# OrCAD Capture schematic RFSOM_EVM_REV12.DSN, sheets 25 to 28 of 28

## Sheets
25 18 QSFP: size A4
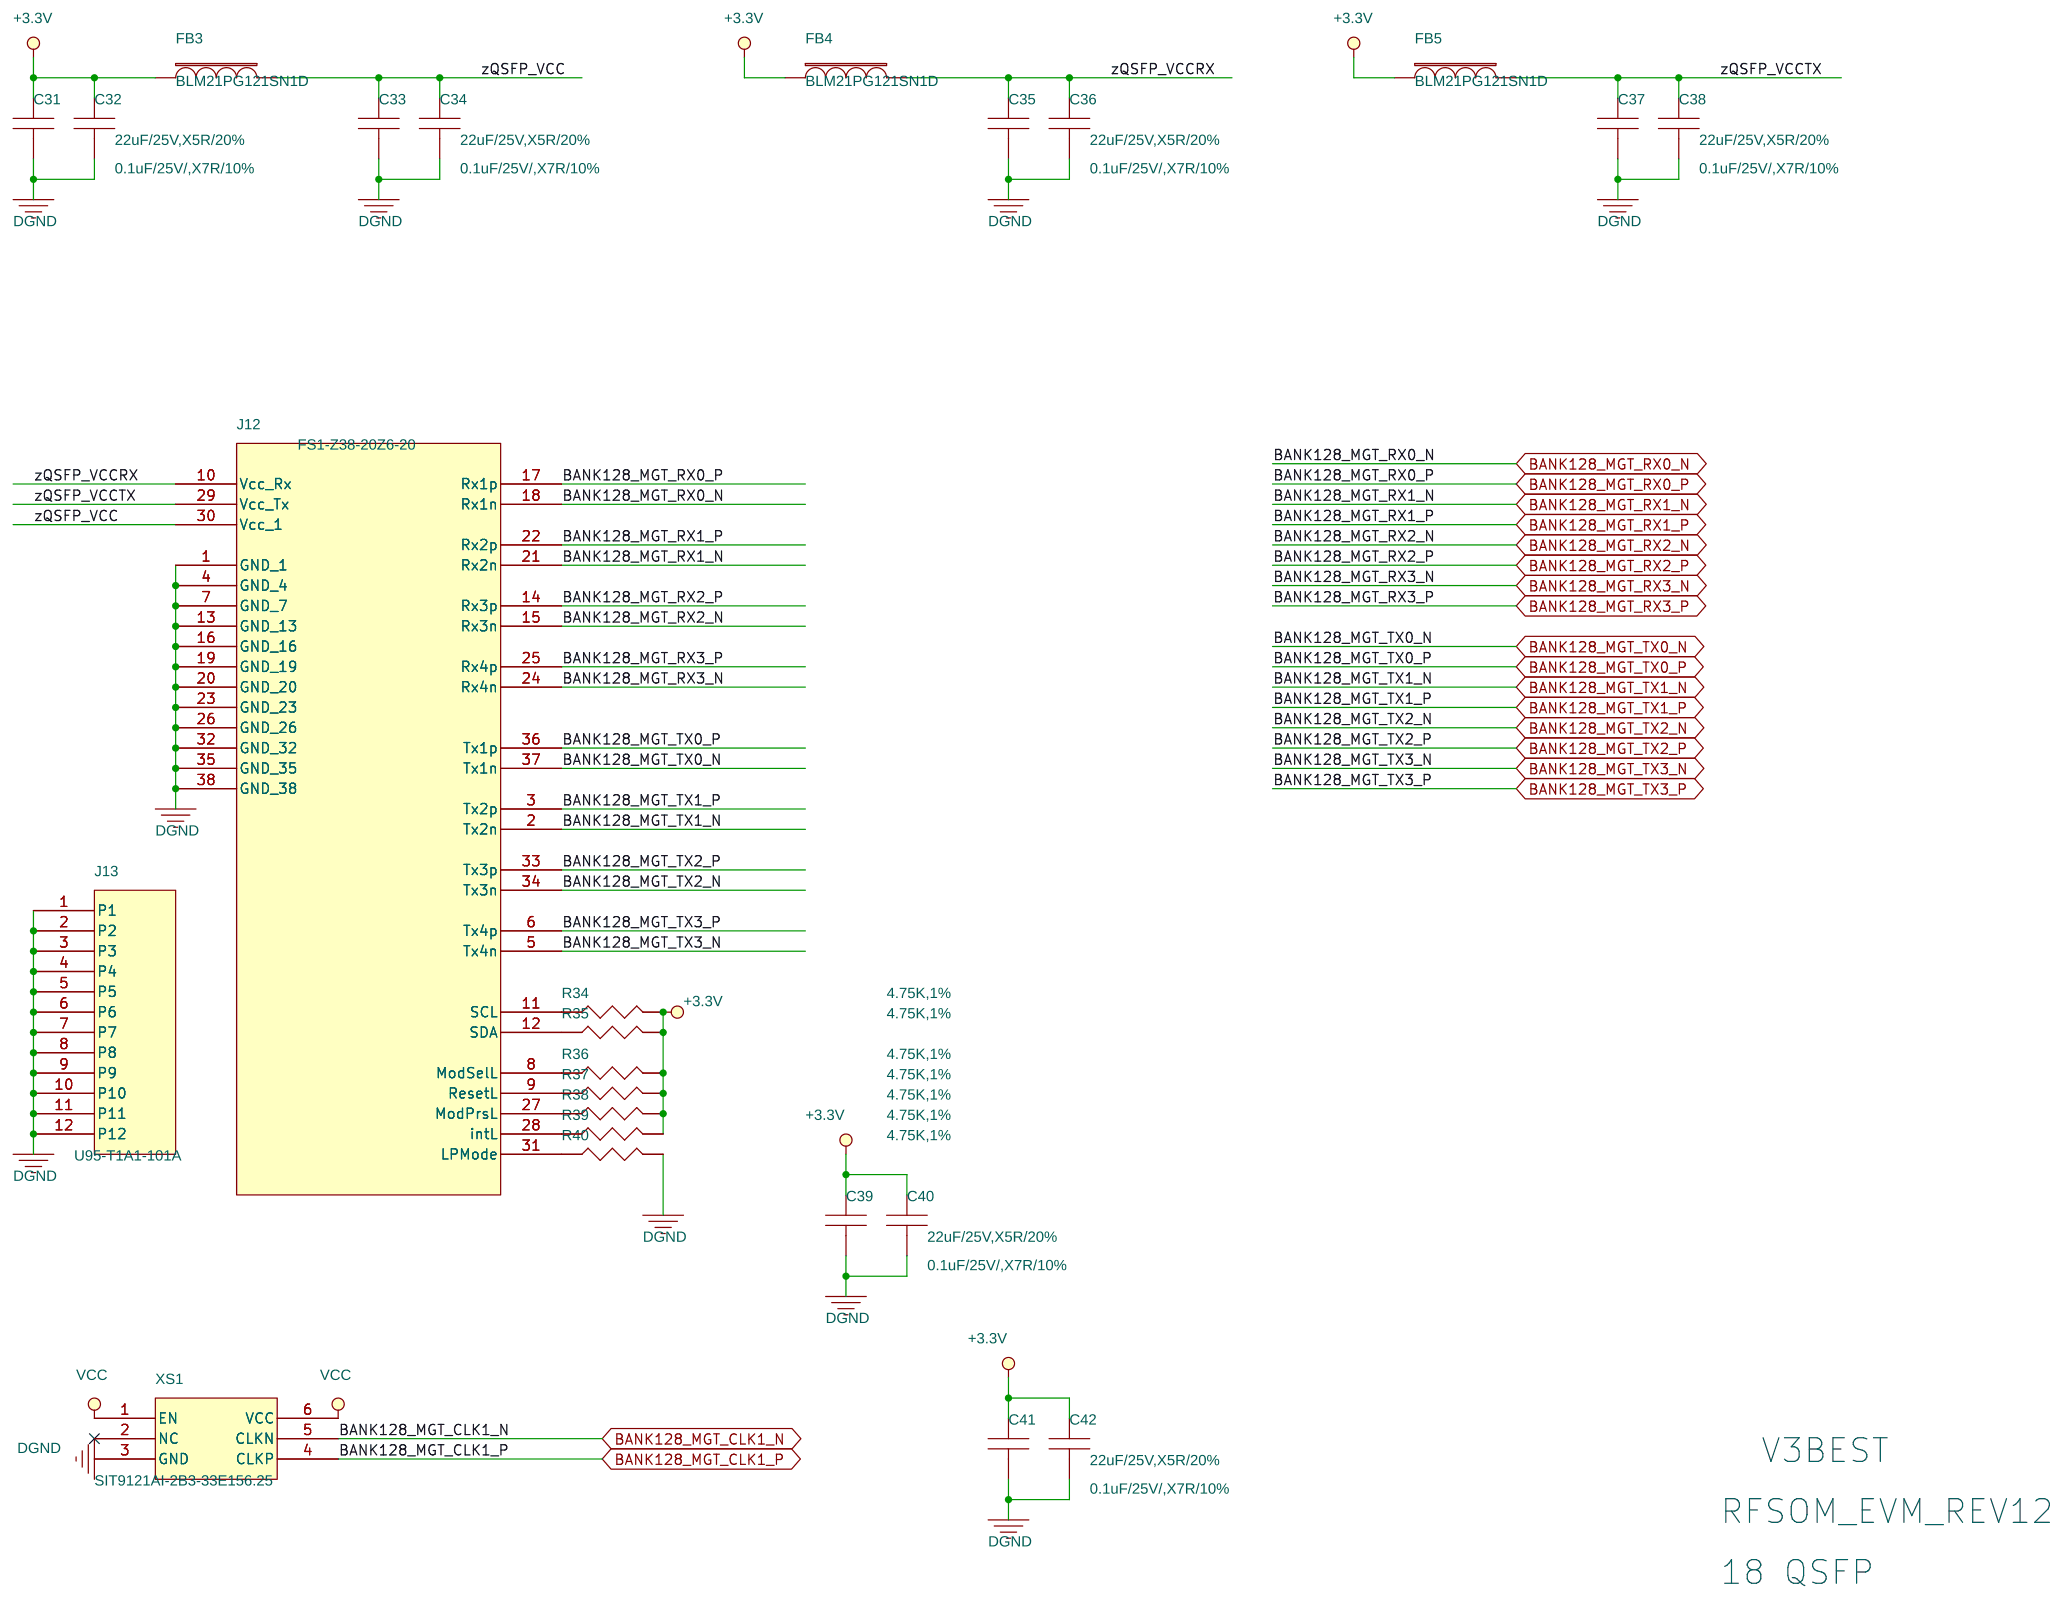
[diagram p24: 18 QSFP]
26 02 SYS_LOGIC
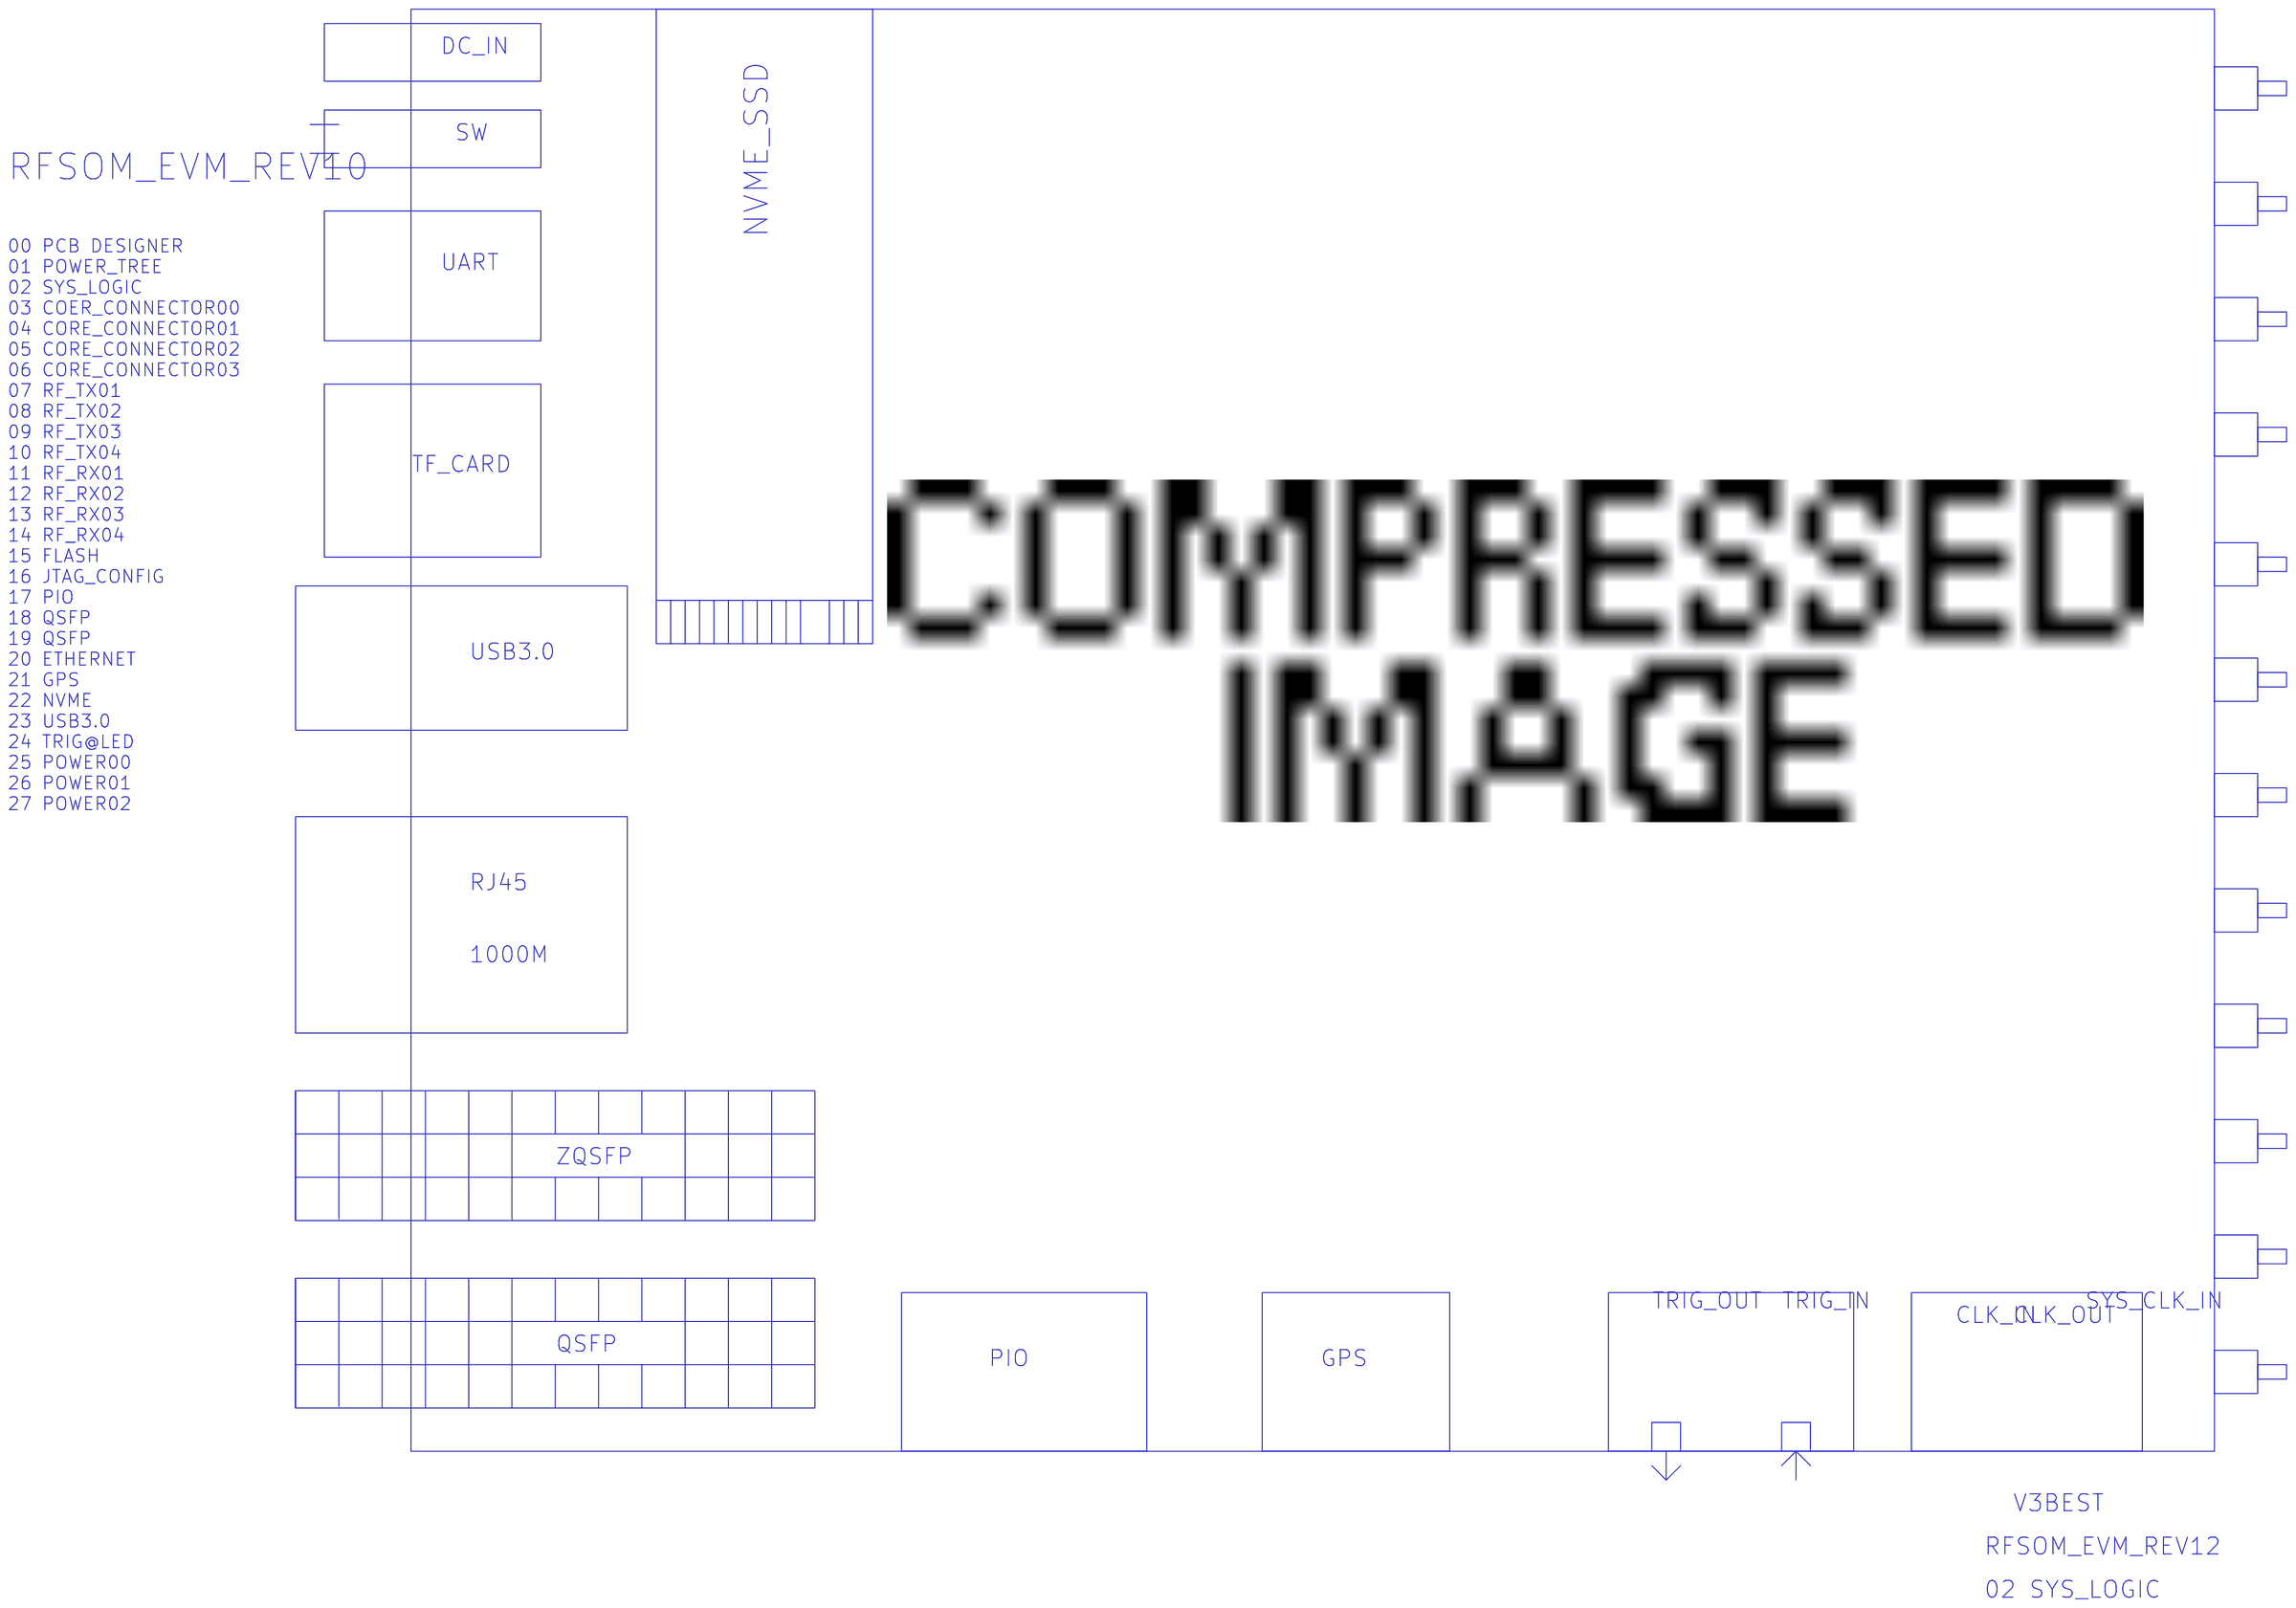
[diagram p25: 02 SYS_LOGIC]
27 16 JTAG_CONFIG: size A4
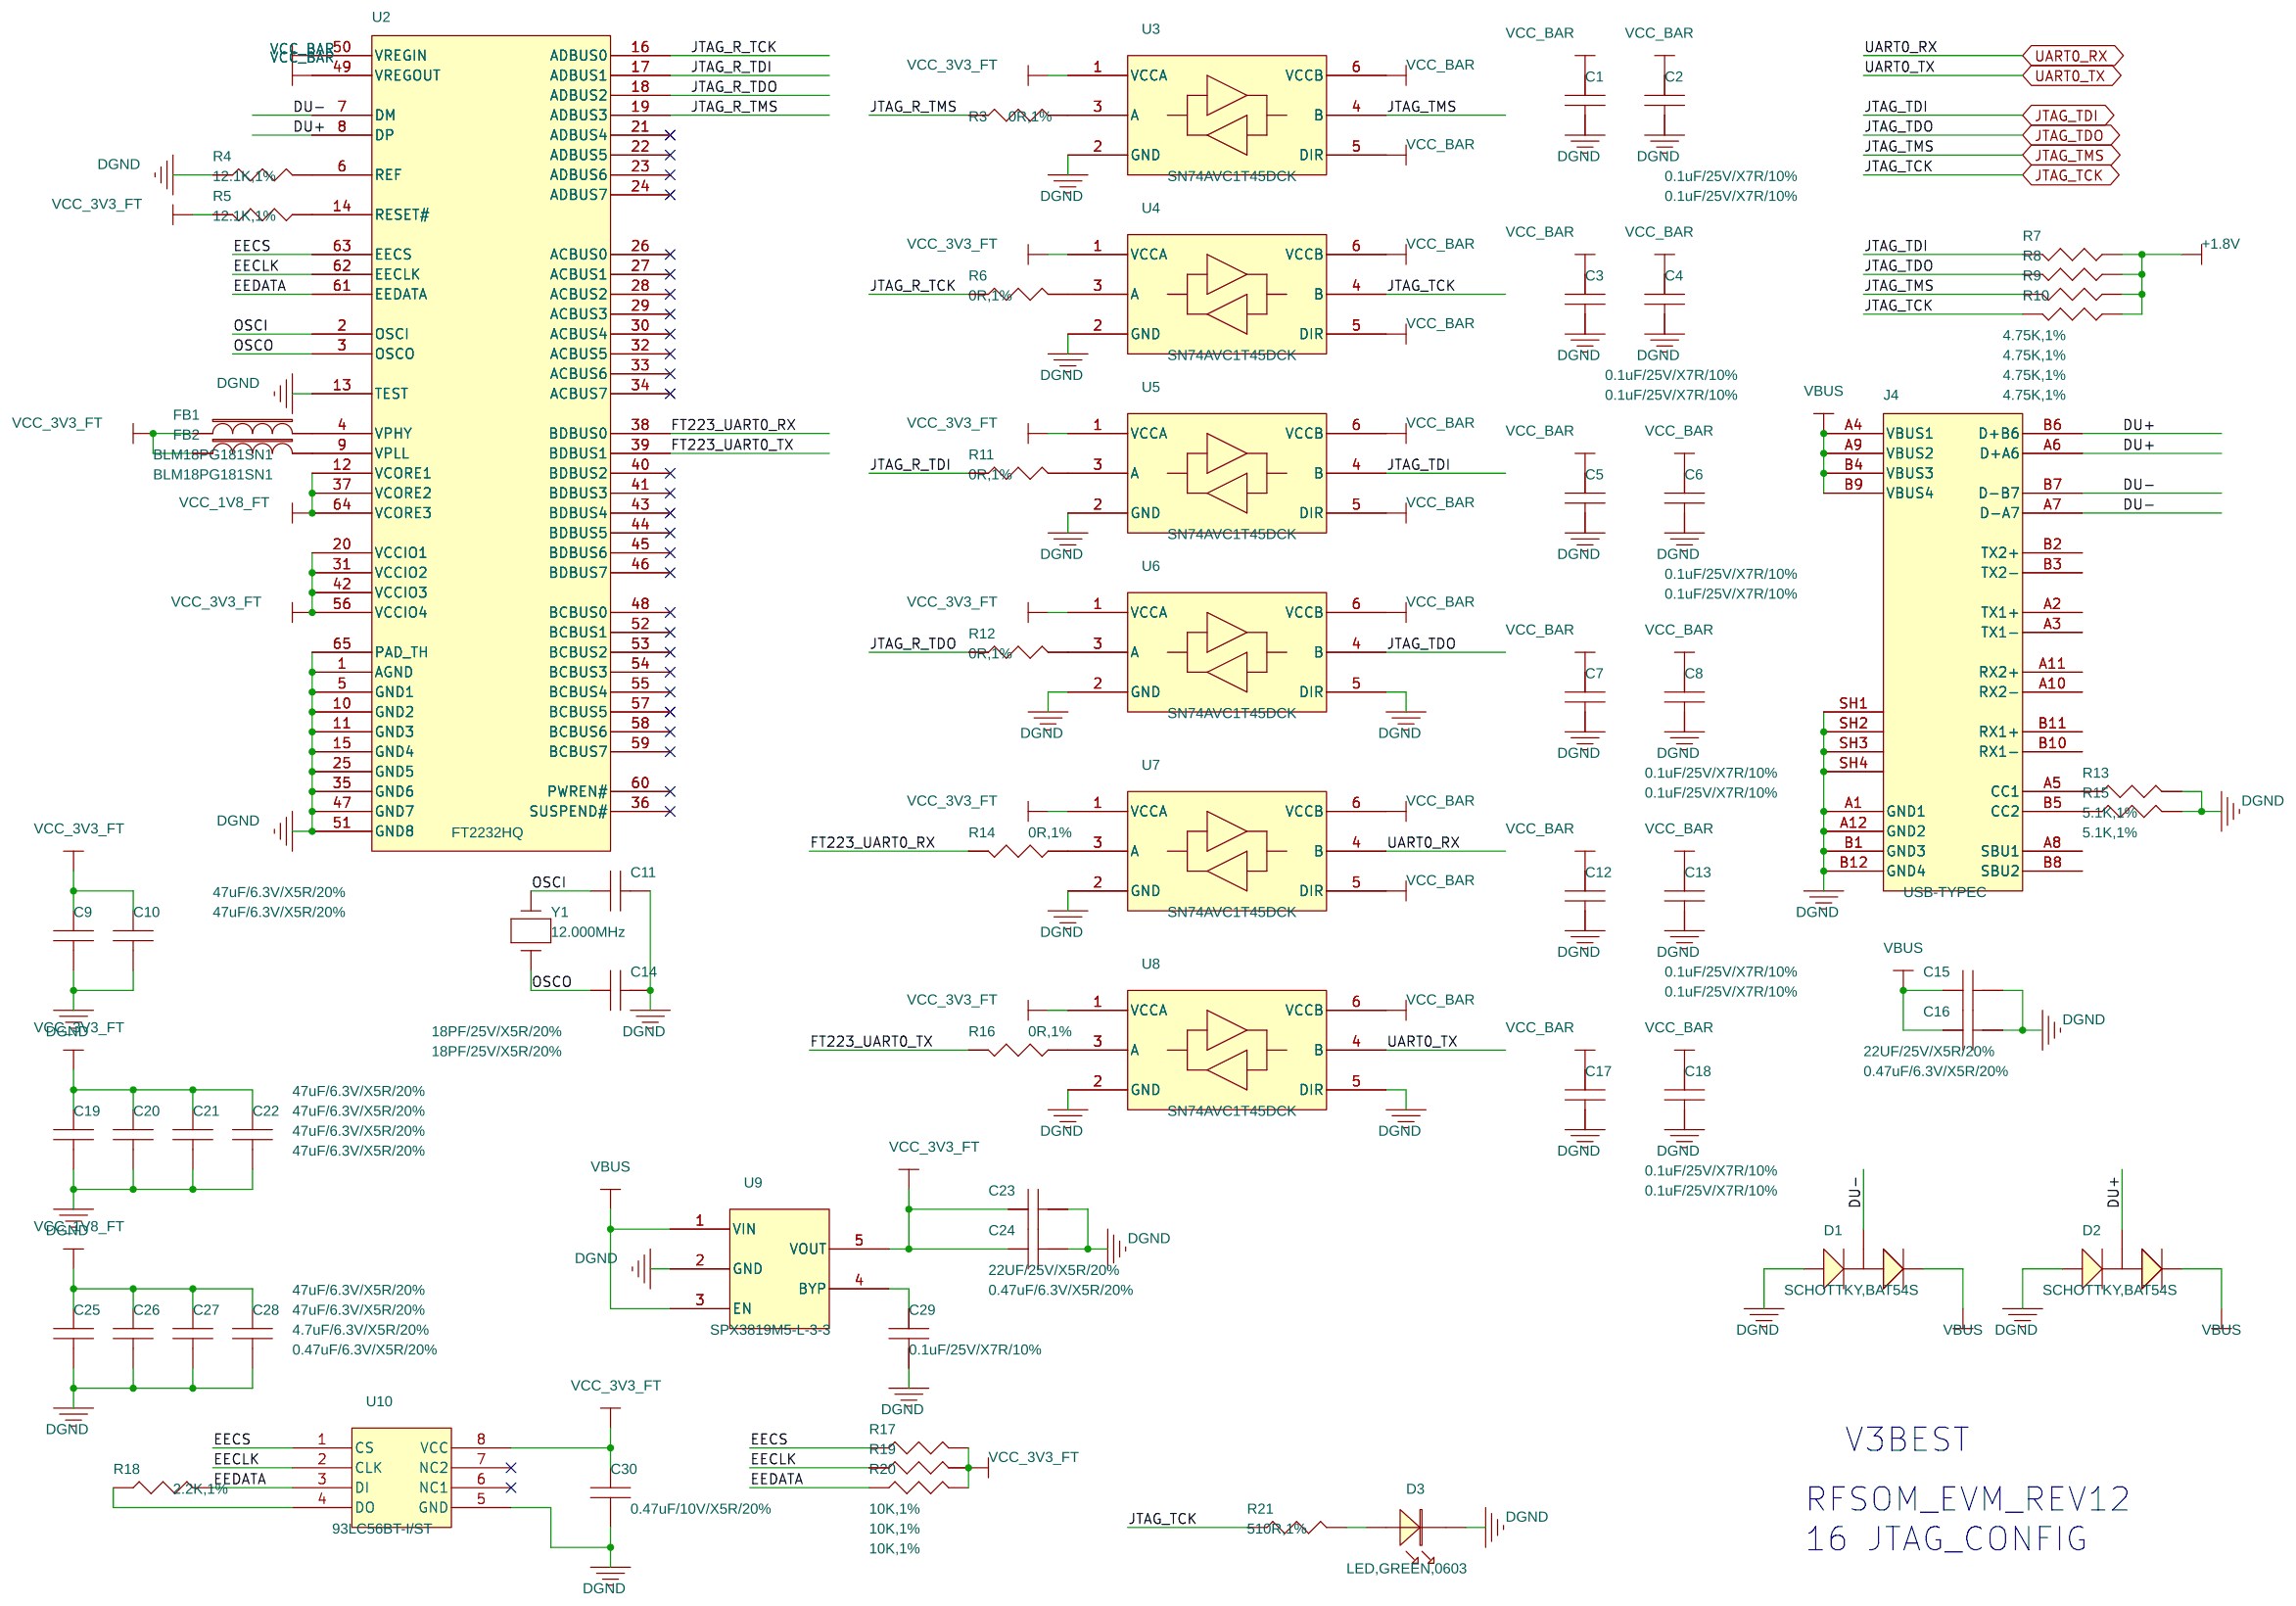
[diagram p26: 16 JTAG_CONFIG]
28 17 PIO: size A4
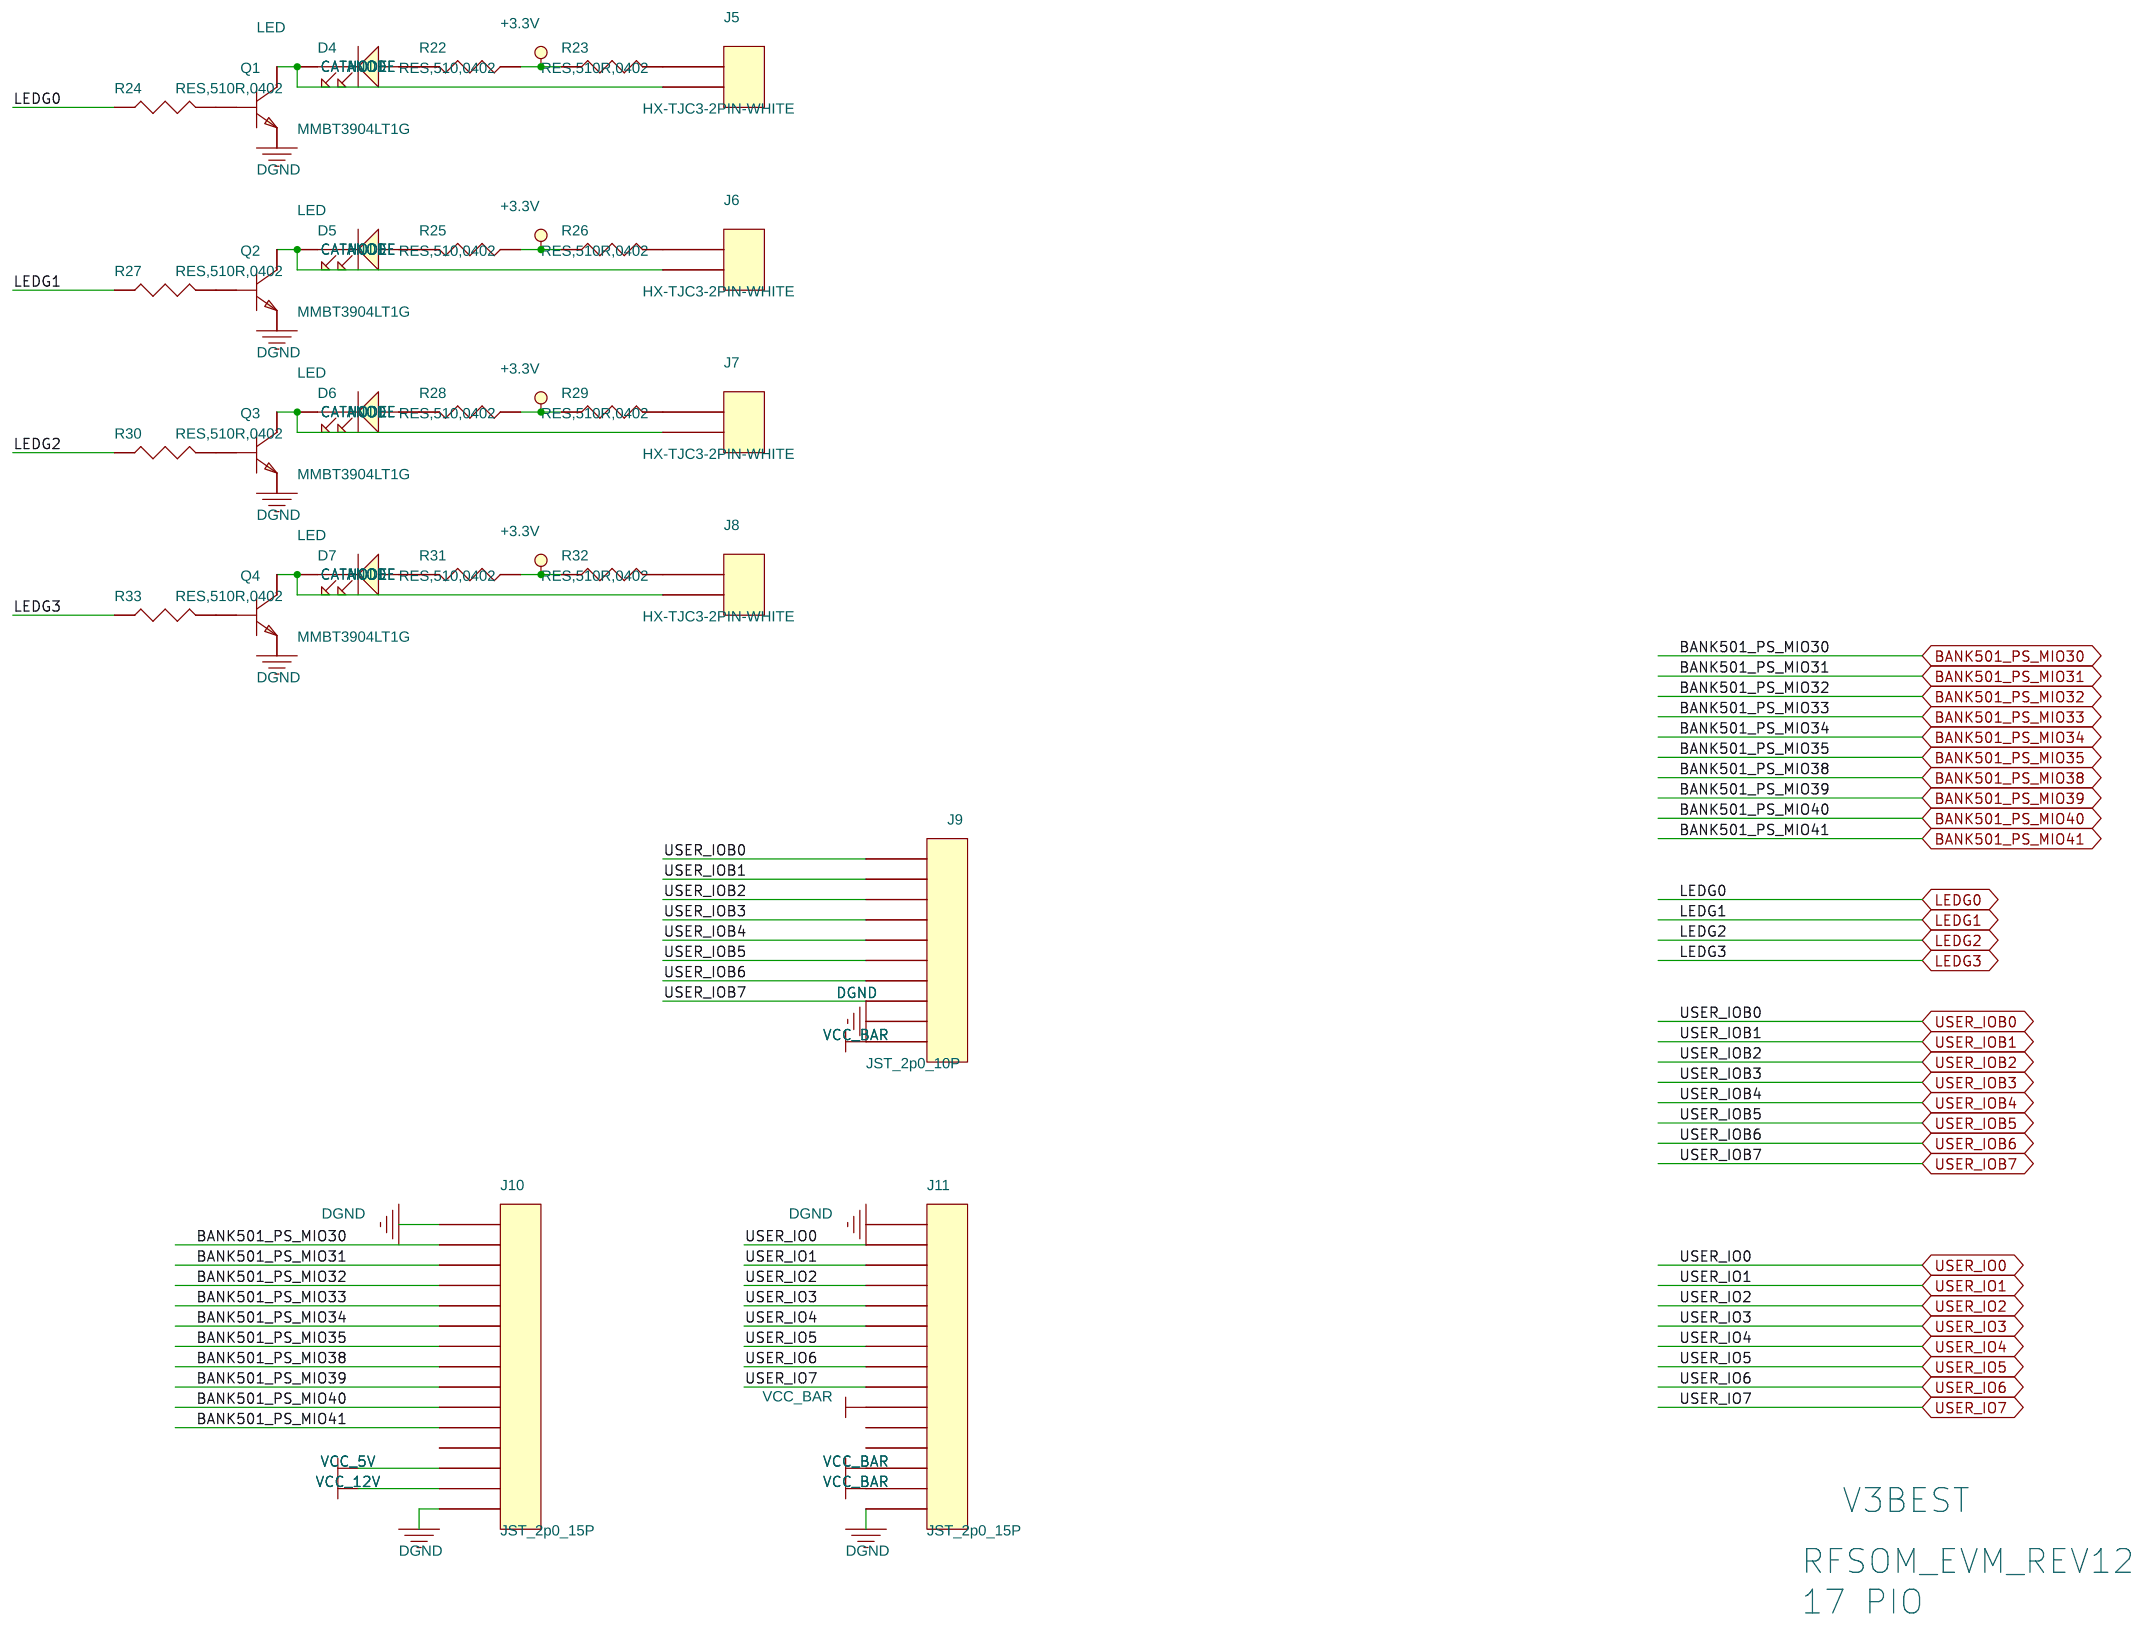
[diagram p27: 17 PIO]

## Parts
sheet 16 JTAG_CONFIG
C1  0.1uF/25V/X7R/10%  [C0402]
C2  0.1uF/25V/X7R/10%  [C0402]
C3  0.1uF/25V/X7R/10%  [C0402]
C4  0.1uF/25V/X7R/10%  [C0402]
C5  0.1uF/25V/X7R/10%  [C0402]
C6  0.1uF/25V/X7R/10%  [C0402]
C7  0.1uF/25V/X7R/10%  [C0402]
C8  0.1uF/25V/X7R/10%  [C0402]
C9  47uF/6.3V/X5R/20%  [C1206]
C10  47uF/6.3V/X5R/20%  [C1206]
C11  18PF/25V/X5R/20%  [C0402]
C12  0.1uF/25V/X7R/10%  [C0402]
C13  0.1uF/25V/X7R/10%  [C0402]
C14  18PF/25V/X5R/20%  [C0402]
C15  22UF/25V/X5R/20%  [C1206]
C16  0.47uF/6.3V/X5R/20%  [C0402]
C17  0.1uF/25V/X7R/10%  [C0402]
C18  0.1uF/25V/X7R/10%  [C0402]
C19  47uF/6.3V/X5R/20%  [C1206]
C20  47uF/6.3V/X5R/20%  [C1206]
C21  47uF/6.3V/X5R/20%  [C0402]
C22  47uF/6.3V/X5R/20%  [C0402]
C23  22UF/25V/X5R/20%  [C1206]
C24  0.47uF/6.3V/X5R/20%  [C0402]
C25  47uF/6.3V/X5R/20%  [C1206]
C26  47uF/6.3V/X5R/20%  [C1206]
C27  4.7uF/6.3V/X5R/20%  [C0402]
C28  0.47uF/6.3V/X5R/20%  [C0402]
C29  0.1uF/25V/X7R/10%  [C0402]
C30  0.47uF/10V/X5R/20%  [C0402]
D1  SCHOTTKY,BAT54S  [SOT23]
D2  SCHOTTKY,BAT54S  [SOT23]
D3  LED,GREEN,0603  [LED-0603]
FB1  BLM18PG181SN1  [FB0805]
FB2  BLM18PG181SN1  [FB0805]
J4  USB-TYPEC  [2012670005]
R3  0R,1%  [R0402]
R4  12.1K,1%  [R0402]
R5  12.1K,1%  [R0402]
R6  0R,1%  [R0402]
R7  4.75K,1%  [R0402]
R8  4.75K,1%  [R0402]
R9  4.75K,1%  [R0402]
R10  4.75K,1%  [R0402]
R11  0R,1%  [R0402]
R12  0R,1%  [R0402]
R13  5.1K,1%  [R0402]
R14  0R,1%  [R0402]
R15  5.1K,1%  [R0402]
R16  0R,1%  [R0402]
R17  10K,1%  [R0402]
R18  2.2K,1%  [0402R]
R19  10K,1%  [R0402]
R20  10K,1%  [R0402]
R21  510R,1%  [R0402]
U2  FT2232HQ  [QFN64]
U3  SN74AVC1T45DCK  [SC70_6]
U4  SN74AVC1T45DCK  [SC70_6]
U5  SN74AVC1T45DCK  [SC70_6]
U6  SN74AVC1T45DCK  [SC70_6]
U7  SN74AVC1T45DCK  [SC70_6]
U8  SN74AVC1T45DCK  [SC70_6]
U9  SPX3819M5-L-3-3  [SOT_25]
U10  93LC56BT-I/ST  [TSSOP8]
Y1  12.000MHz  [CRYSTAL_5X3P2]
sheet 17 PIO
D4  LED  [0603LED]
D5  LED  [0603LED]
D6  LED  [0603LED]
D7  LED  [0603LED]
J5  HX-TJC3-2PIN-WHITE  [HX-TJC3-2PIN-WHITE]
J6  HX-TJC3-2PIN-WHITE  [HX-TJC3-2PIN-WHITE]
J7  HX-TJC3-2PIN-WHITE  [HX-TJC3-2PIN-WHITE]
J8  HX-TJC3-2PIN-WHITE  [HX-TJC3-2PIN-WHITE]
J9  JST_2p0_10P  [SIP10_2-0MM_S]
J10  JST_2p0_15P  [SIP15_2-0MM_S]
J11  JST_2p0_15P  [SIP15_2-0MM_S]
Q1  MMBT3904LT1G  [SOT_23]
Q2  MMBT3904LT1G  [SOT_23]
Q3  MMBT3904LT1G  [SOT_23]
Q4  MMBT3904LT1G  [SOT_23]
R22  RES,510,0402  [R0402]
R23  RES,510R,0402  [R0402]
R24  RES,510R,0402  [R0402]
R25  RES,510,0402  [R0402]
R26  RES,510R,0402  [R0402]
R27  RES,510R,0402  [R0402]
R28  RES,510,0402  [R0402]
R29  RES,510R,0402  [R0402]
R30  RES,510R,0402  [R0402]
R31  RES,510,0402  [R0402]
R32  RES,510R,0402  [R0402]
R33  RES,510R,0402  [R0402]
sheet 18 QSFP
C31  22uF/25V,X5R/20%  [C1206]
C32  0.1uF/25V/,X7R/10%  [C0402]
C33  22uF/25V,X5R/20%  [C1206]
C34  0.1uF/25V/,X7R/10%  [C0402]
C35  22uF/25V,X5R/20%  [C1206]
C36  0.1uF/25V/,X7R/10%  [C0402]
C37  22uF/25V,X5R/20%  [C1206]
C38  0.1uF/25V/,X7R/10%  [C0402]
C39  22uF/25V,X5R/20%  [C1206]
C40  0.1uF/25V/,X7R/10%  [C0402]
C41  22uF/25V,X5R/20%  [C1206]
C42  0.1uF/25V/,X7R/10%  [C0402]
FB3  BLM21PG121SN1D  [FB0805]
FB4  BLM21PG121SN1D  [FB0805]
FB5  BLM21PG121SN1D  [FB0805]
J12  FS1-Z38-20Z6-20  [QSFP28_CON]
J13  U95-T1A1-101A  [U95-T1N1-101A]
R34  4.75K,1%  [R0402]
R35  4.75K,1%  [R0402]
R36  4.75K,1%  [R0402]
R37  4.75K,1%  [R0402]
R38  4.75K,1%  [R0402]
R39  4.75K,1%  [R0402]
R40  4.75K,1%  [R0402]
XS1  SIT9121AI-2B3-33E156.25  [XTALSMD_3225_DP]

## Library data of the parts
C1-C42 = CAP
D1 D2 = SCHOTTKY,BAT54S
D3 = LED,GREEN,0603
FB1 FB2 = BLM18PG181SN1D
J4 = USB-TYPEC
R3-R13 R15 R17 R19-R22 R25 R28 R31 = RES-H
R14 R16 R18 R23 R24 R26 R27 R29 R30 R32-R40 = RES
U2 = FT2232HQ
U3-U8 = SN74AVC1T45
U9 = SPX3819M5-L-3-3
U10 = 93LC56BT-I_ST
Y1 = CRYSTAL
D4-D7 = LED
J5-J8 = HX-TJC3-2PIN-WHITE
J9 = HEADER_10
J10 J11 = JST_2p0_15
Q1-Q4 = MMBT3904LT1G
FB3-FB5 = BLM21PG121SN1D
J12 = QSFP28-FS1-Z38-20Z6-20_0
J13 = U95-T1A1-101A
XS1 = SIT9121

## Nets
+1.8V: C2.1 C4.1 C6.1 C8.1 R7.1 R8.1 R9.1 R10.1 U3.6(VCCB) U4.6(VCCB) U5.6(VCCB) U6.6(VCCB) ; also on sheet 5 20 21
+3.3V: C13.1 C18.1 C31.1 C32.1 C39.1 C40.1 C41.1 C42.1 FB3.1 FB4.1 FB5.1 J11.10 R22.1 R23.1 R25.1 R26.1 R28.1 R29.1 R31.1 R32.1 R34.2 R35.2 R36.2 R37.2 R38.2 R39.2 U7.6(VCCB) U8.6(VCCB) XS1.1(EN) XS1.6(VCC) ; also on sheet 2 3 4 5 7 20 21 23 24
DGND: C1.2 C2.2 C3.2 C4.2 C5.2 C6.2 C7.2 C8.2 C9.2 C10.2 C11.2 C12.2 C13.2 C14.2 C15.2 C16.2 C17.2 C18.2 C19.2 C20.2 C21.2 C22.2 C23.2 C24.2 C25.2 C26.2 C27.2 C28.2 C29.2 C30.2 C31.2 C32.2 C33.2 C34.2 C35.2 C36.2 C37.2 C38.2 C39.2 C40.2 C41.2 C42.2 D1.1 D2.1 D3.2(K) J4.A1(GND1) J4.A12(GND2) J4.B1(GND3) J4.B12(GND4) J4.SH1 J4.SH2 J4.SH3 J4.SH4 J9.9 J10.1 J10.15 J11.1 J11.15 J12.1(GND) J12.4(GND) J12.7(GND) J12.13(GND) J12.16(GND) J12.19(GND) J12.20(GND) J12.23(GND) J12.26(GND) J12.32(GND) J12.35(GND) J12.38(GND) J13.1(P1) J13.2(P2) J13.3(P3) J13.4(P4) J13.5(P5) J13.6(P6) J13.7(P7) J13.8(P8) J13.9(P9) J13.10(P10) J13.11(P11) J13.12(P12) Q1.2(E) Q2.2(E) Q3.2(E) Q4.2(E) R4.1 R13.2 R15.2 R40.2 U2.1(AGND) U2.5(GND1) U2.10(GND2) U2.11(GND3) U2.13(TEST) U2.15(GND4) U2.25(GND5) U2.35(GND6) U2.47(GND7) U2.51(GND8) U2.65(PAD_TH) U3.2(GND) U4.2(GND) U5.2(GND) U6.2(GND) U6.5(DIR) U7.2(GND) U8.2(GND) U8.5(DIR) U9.2(GND) U10.5(GND) XS1.3(GND) ; also on sheet 2 3 4 5 6 7 8 9 10 11 12 13 14 15 16 18 20 21 23 24
VBUS: C15.1 C16.1 D1.2 D2.2 J4.A4(VBUS1) J4.A9(VBUS2) J4.B4(VBUS3) J4.B9(VBUS4) U9.1(VIN) U9.3(EN)
VCC_1V8_FT: C25.1 C26.1 C27.1 C28.1 U2.12(VCORE1) U2.37(VCORE2) U2.49(VREGOUT) U2.64(VCORE3)
VCC_3V3_FT: C1.1 C3.1 C5.1 C7.1 C9.1 C10.1 C12.1 C17.1 C19.1 C20.1 C21.1 C22.1 C23.1 C24.1 C30.1 FB1.1 FB2.1 R5.2 R17.2 R19.2 R20.2 U2.20(VCCIO1) U2.31(VCCIO2) U2.42(VCCIO3) U2.50(VREGIN) U2.56(VCCIO4) U3.1(VCCA) U3.5(DIR) U4.1(VCCA) U4.5(DIR) U5.1(VCCA) U5.5(DIR) U6.1(VCCA) U7.1(VCCA) U7.5(DIR) U8.1(VCCA) U9.5(VOUT) U10.8(VCC)
VCC_5V: J10.13 J11.13 ; also on sheet 6 16 18 20
VCC_12V: J9.10 J10.14 J11.14 ; also on sheet 4 5 6
BANK128_MGT_CLK1_N: XS1.5(CLKN) ; also on sheet 17
BANK128_MGT_CLK1_P: XS1.4(CLKP) ; also on sheet 17
BANK128_MGT_RX0_N: J12.18(Rx1n) ; also on sheet 17
BANK128_MGT_RX0_P: J12.17(Rx1p) ; also on sheet 17
BANK128_MGT_RX1_N: J12.21(Rx2n) ; also on sheet 17
BANK128_MGT_RX1_P: J12.22(Rx2p) ; also on sheet 17
BANK128_MGT_RX2_N: J12.15(Rx3n) ; also on sheet 17
BANK128_MGT_RX2_P: J12.14(Rx3p) ; also on sheet 17
BANK128_MGT_RX3_N: J12.24(Rx4n) ; also on sheet 17
BANK128_MGT_RX3_P: J12.25(Rx4p) ; also on sheet 17
BANK128_MGT_TX0_N: J12.37(Tx1n) ; also on sheet 17
BANK128_MGT_TX0_P: J12.36(Tx1p) ; also on sheet 17
BANK128_MGT_TX1_N: J12.2(Tx2n) ; also on sheet 17
BANK128_MGT_TX1_P: J12.3(Tx2p) ; also on sheet 17
BANK128_MGT_TX2_N: J12.34(Tx3n) ; also on sheet 17
BANK128_MGT_TX2_P: J12.33(Tx3p) ; also on sheet 17
BANK128_MGT_TX3_N: J12.5(Tx4n) ; also on sheet 17
BANK128_MGT_TX3_P: J12.6(Tx4p) ; also on sheet 17
BANK501_PS_MIO30: J10.2 ; also on sheet 17
BANK501_PS_MIO31: J10.3 ; also on sheet 17
BANK501_PS_MIO32: J10.4 ; also on sheet 17
BANK501_PS_MIO33: J10.5 ; also on sheet 17
BANK501_PS_MIO34: J10.6 ; also on sheet 17
BANK501_PS_MIO35: J10.7 ; also on sheet 17
BANK501_PS_MIO38: J10.8 ; also on sheet 17
BANK501_PS_MIO39: J10.9 ; also on sheet 17
BANK501_PS_MIO40: J10.10 ; also on sheet 17
BANK501_PS_MIO41: J10.11 ; also on sheet 17
DU+: D2.3 J4.A6(D+A6) J4.B6(D+B6) U2.8(DP)
DU-: D1.3 J4.A7(D-A7) J4.B7(D-B7) U2.7(DM)
EECLK: R19.1 U2.62(EECLK) U10.2(CLK)
EECS: R17.1 U2.63(EECS) U10.1(CS)
EEDATA: R18.2 R20.1 U2.61(EEDATA) U10.3(DI)
FT223_UART0_RX: R14.1 U2.38(BDBUS0)
FT223_UART0_TX: R16.1 U2.39(BDBUS1)
JTAG_R_TCK: R6.1 U2.16(ADBUS0)
JTAG_R_TDI: R11.1 U2.17(ADBUS1)
JTAG_R_TDO: R12.1 U2.18(ADBUS2)
JTAG_R_TMS: R3.1 U2.19(ADBUS3)
JTAG_TCK: R10.2 R21.1 U4.4(B) ; also on sheet 17
JTAG_TDI: R7.2 U5.4(B) ; also on sheet 17
JTAG_TDO: R8.2 U6.4(B) ; also on sheet 17
JTAG_TMS: R9.2 U3.4(B) ; also on sheet 17
LEDG0: R24.1 ; also on sheet 19
LEDG1: R27.1 ; also on sheet 19
LEDG2: R30.1 ; also on sheet 19
LEDG3: R33.1 ; also on sheet 19
OSCI: C11.1 U2.2(OSCI) Y1.2
OSCO: C14.1 U2.3(OSCO) Y1.1
UART0_RX: U7.4(B) ; also on sheet 17
UART0_TX: U8.4(B) ; also on sheet 17
USER_IO0: J11.2 ; also on sheet 19
USER_IO1: J11.3 ; also on sheet 19
USER_IO2: J11.4 ; also on sheet 19
USER_IO3: J11.5 ; also on sheet 19
USER_IO4: J11.6 ; also on sheet 19
USER_IO5: J11.7 ; also on sheet 19
USER_IO6: J11.8 ; also on sheet 19
USER_IO7: J11.9 ; also on sheet 19
USER_IOB0: J9.1 ; also on sheet 19
USER_IOB1: J9.2 ; also on sheet 19
USER_IOB2: J9.3 ; also on sheet 19
USER_IOB3: J9.4 ; also on sheet 19
USER_IOB4: J9.5 ; also on sheet 19
USER_IOB5: J9.6 ; also on sheet 19
USER_IOB6: J9.7 ; also on sheet 19
USER_IOB7: J9.8 ; also on sheet 19
zQSFP_VCC: C33.1 C34.1 FB3.2 J12.30(Vcc_1)
zQSFP_VCCRX: C35.1 C36.1 FB4.2 J12.10(Vcc_Rx)
zQSFP_VCCTX: C37.1 C38.1 FB5.2 J12.29(Vcc_Tx)
N22531080: C29.1 U9.4(BYP)
N22531228: R18.1 U10.4(DO)
N22531283: D3.1(A) R21.2
N22613335: D4.2(CATHODE) J5.2 Q1.3(C)
N22613341: D5.2(CATHODE) J6.2 Q2.3(C)
N22613343: D6.2(CATHODE) J7.2 Q3.3(C)
N22613345: D7.2(CATHODE) J8.2 Q4.3(C)
N23202387: R6.2 U4.3(A)
N23202395: R3.2 U3.3(A)
N23202396: R14.2 U7.3(A)
N23202399: R11.2 U5.3(A)
N23202401: R4.2 U2.6(REF)
N23202404: FB1.2 U2.4(VPHY)
N23202405: FB2.2 U2.9(VPLL)
N23202406: J4.A5(CC1) R13.1
N23202412: R16.2 U8.3(A)
N23202413: R12.2 U6.3(A)
N23202414: J4.B5(CC2) R15.1
N23202416: R5.1 U2.14(RESET#)
N23202547: D7.1(ANODE) R31.2
N23202548: Q4.1(B) R33.2
N23202549: J7.1 R29.2
N23202550: D5.1(ANODE) R25.2
N23202551: D6.1(ANODE) R28.2
N23202552: J5.1 R23.2
N23202553: Q1.1(B) R24.2
N23202554: J6.1 R26.2
N23202555: Q3.1(B) R30.2
N23202556: Q2.1(B) R27.2
N23202557: J8.1 R32.2
N23202558: D4.1(ANODE) R22.2
N23202786: J12.12(SDA) R35.1
N23202787: J12.31(LPMode) R40.1
N23202789: J12.28(intL) R39.1
N23202790: J12.27(ModPrsL) R38.1
N23202791: J12.11(SCL) R34.1
N23202796: J12.9(ResetL) R37.1
N23202797: J12.8(ModSelL) R36.1

Not connected (* = marked no-connect by the designer): J4 A2(TX1+) A3(TX1-) A8(SBU1) A10(RX2-) A11(RX2+) B2(TX2+) B3(TX2-) B8(SBU2) B10(RX1-) B11(RX1+); J10 12; J11 11 12; U2 21(ADBUS4)* 22(ADBUS5)* 23(ADBUS6)* 24(ADBUS7)* 26(ACBUS0)* 27(ACBUS1)* 28(ACBUS2)* 29(ACBUS3)* 30(ACBUS4)* 32(ACBUS5)* 33(ACBUS6)* 34(ACBUS7)* 36(SUSPEND#)* 40(BDBUS2)* 41(BDBUS3)* 43(BDBUS4)* 44(BDBUS5)* 45(BDBUS6)* 46(BDBUS7)* 48(BCBUS0)* 52(BCBUS1)* 53(BCBUS2)* 54(BCBUS3)* 55(BCBUS4)* 57(BCBUS5)* 58(BCBUS6)* 59(BCBUS7)* 60(PWREN#)*; U10 6(NC1)* 7(NC2)*; XS1 2(NC)*

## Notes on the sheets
sheet 25
- V3BEST
- RFSOM_EVM_REV12
- 18 QSFP
sheet 26
- DC_IN
- SW
- RFSOM_EVM_REV10
- 00 PCB DESIGNER
  01 POWER_TREE
  02 SYS_LOGIC
  03 COER_CONNECTOR00
  04 CORE_CONNECTOR01
  05 CORE_CONNECTOR02
  06 CORE_CONNECTOR03
  07 RF_TX01
  08 RF_TX02
  09 RF_TX03
  10 RF_TX04
  11 RF_RX01
  12 RF_RX02
  13 RF_RX03
  14 RF_RX04
  15 FLASH
  16 JTAG_CONFIG
  17 PIO
  18 QSFP
  19 QSFP
  20 ETHERNET
  21 GPS
  22 NVME
  23 USB3.0
  24 TRIG@LED
  25 POWER00
  26 POWER01
  27 POWER02
- UART
- NVME_SSD
- TF_CARD
- USB3.0
- RJ45
- 1000M
- ZQSFP
- TRIG_OUT
- TRIG_IN
- SYS_CLK_IN
- CLK_IN
- CLK_OUT
- QSFP
- PIO
- GPS
- V3BEST
- RFSOM_EVM_REV12
- 02 SYS_LOGIC
sheet 27
- V3BEST
- RFSOM_EVM_REV12
- 16 JTAG_CONFIG
sheet 28
- V3BEST
- RFSOM_EVM_REV12
- 17 PIO
